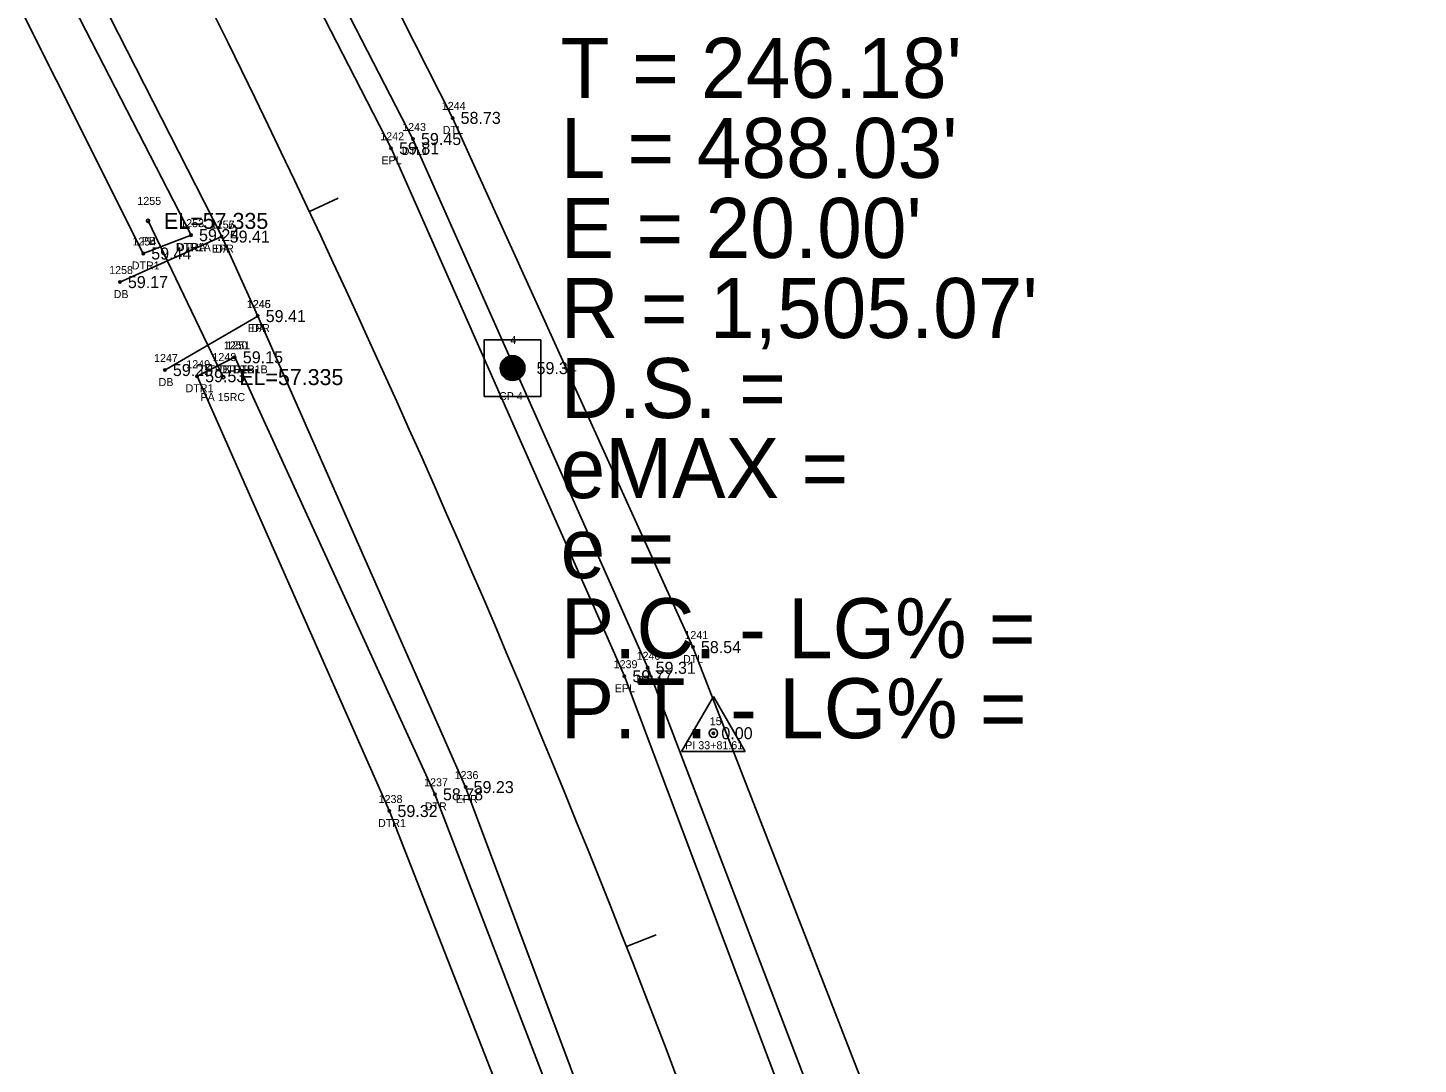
# Model space of a CAD drawing. Extents: x 2396531 to 2397633, y 770203 to 772837.
# Drawn here: x 2397412.4 to 2397586.1, y 770458.3 to 770587.8 of the extents above; entities that cross this region are included whole.
import ezdxf

# ---------------------------------------------------------------- set-up
doc = ezdxf.new("R2010")
doc.units = 0
for name, color, linetype in [('RD_EX_DR_Pipe', 7, 'Continuous'), ('RD_EX_DR_Pipe_txCode', 7, 'Continuous'), ('RD_EX_Driveway', 7, 'Continuous'), ('RD_EX_Driveway_txCode', 7, 'Continuous'), ('RD_EX_H2O', 7, 'Continuous'), ('RD_EX_H2O_txCode', 7, 'Continuous'), ('RD_EX_Road', 7, 'Continuous'), ('RD_EX_Road_txCode', 7, 'Continuous'), ('RD_EX_TX_Driveway_ELEV', 7, 'Continuous'), ('RD_EX_TX_H2O_ELEV', 7, 'Continuous'), ('RD_EX_TX_Road_ELEV', 7, 'Continuous'), ('RD_HC_Cl', 7, 'Continuous'), ('RD_HC_Data', 7, 'Continuous'), ('RD_HC_Data_Tic', 7, 'Continuous'), ('RD_HC_Survey', 7, 'Continuous'), ('RD_HC_Survey_ELEV', 7, 'Continuous'), ('RD_HC_Survey_txCode', 7, 'Continuous'), ('RD_HC_txCode', 7, 'Continuous'), ('RD_SMD_Locator', 7, 'Continuous'), ('RD_TX_Pipe_ElevEX', 7, 'Continuous')]:
    doc.layers.add(name, color=color, linetype=linetype)

msp = doc.modelspace()

# ---------------------------------------------------------------- linework, layer by layer
at = {"layer": 'RD_EX_DR_Pipe'}
msp.add_line((2397436.85, 770544.12), (2397427.46, 770563.63), dxfattribs=at)
at = {"layer": 'RD_EX_Driveway'}
for p, q in [((2397436.66, 770561.67), (2397423.94, 770555.99)), ((2397441.16, 770551.74), (2397429.56, 770545))]:
    msp.add_line(p, q, dxfattribs=at)
at = {"layer": 'RD_EX_H2O'}
for points in [[(2397586.15, 770211.51), (2397567.31, 770287.61), (2397548.79, 770357.79), (2397525.19, 770434.22), (2397495.53, 770510.39), (2397465.51, 770576.5), (2397430.55, 770645.5), (2397380.29, 770734.7), (2397327.01, 770824.44), (2397291.42, 770882.36)], [(2397579.43, 770209.93), (2397561.1, 770285.3), (2397543.19, 770356.19), (2397518.98, 770431.67), (2397489.88, 770507.8), (2397460.56, 770573.86), (2397425.02, 770642.83), (2397373.6, 770730.3), (2397319.08, 770819.92), (2397284.14, 770878.8)], [(2397432.83, 770561.85), (2397399.16, 770627.27), (2397350.75, 770711.42), (2397293.36, 770805.09), (2397257.48, 770863.23)], [(2397432.83, 770561.85), (2397426.86, 770559.56), (2397394.23, 770624.59), (2397345.55, 770708.21), (2397287.31, 770801.51), (2397251.15, 770859.33)], [(2397544.21, 770204.98), (2397524.44, 770279.37), (2397505.98, 770346.02), (2397484.83, 770420.44), (2397457.62, 770489.91), (2397433.59, 770544.23), (2397438.3, 770546.59)], [(2397549.62, 770204.86), (2397531.98, 770280.53), (2397513.08, 770348.26), (2397490.2, 770421.93), (2397463.3, 770492), (2397438.3, 770546.59)]]:
    msp.add_lwpolyline(points, dxfattribs=at)
at = {"layer": 'RD_EX_Road'}
for points in [[(2397576.88, 770209.21), (2397558.85, 770284.47), (2397539.93, 770354.87), (2397515.81, 770430.13), (2397486.97, 770506.75), (2397457.82, 770572.7), (2397422.37, 770641.75), (2397371.16, 770729.12), (2397316.57, 770818.52), (2397280.76, 770876.73)], [(2397553.19, 770205.48), (2397535.12, 770280.96), (2397517, 770349.24), (2397493.4, 770422.78), (2397467.13, 770492.9), (2397441.16, 770551.74), (2397436.66, 770561.67), (2397402.21, 770629.28), (2397353, 770712.83), (2397296, 770806.32), (2397260.16, 770864.73)]]:
    msp.add_lwpolyline(points, dxfattribs=at)
at = {"layer": 'RD_HC_Cl'}
msp.add_arc((2396086.26, 769922.93), 1505.07, 12.92958, 31.50817, dxfattribs=at)
at = {"layer": 'RD_HC_Data'}
for p, q in [((2397494.12, 770497.33), (2397498.09, 770504.21)), ((2397498.09, 770504.21), (2397502.06, 770497.33)), ((2397494.12, 770497.33), (2397502.06, 770497.33))]:
    msp.add_line(p, q, dxfattribs=at)
msp.add_circle((2397498.09, 770499.63), 0.529, dxfattribs=at)
at = {"layer": 'RD_HC_Data_Tic'}
for p, q in [((2397447.61, 770564.79), (2397451.23, 770566.49)), ((2397487.22, 770472.99), (2397490.94, 770474.45))]:
    msp.add_line(p, q, dxfattribs=at)
at = {"layer": 'RD_HC_Survey'}
for p, q in [((2397472.09, 770543.98), (2397472.09, 770546.5)), ((2397472.14, 770543.95), (2397472.14, 770546.54)), ((2397472.19, 770543.92), (2397472.19, 770546.57)), ((2397472.24, 770543.89), (2397472.24, 770546.6)), ((2397472.29, 770543.86), (2397472.29, 770546.62)), ((2397472.34, 770543.84), (2397472.34, 770546.65)), ((2397472.39, 770543.81), (2397472.39, 770546.67)), ((2397472.44, 770543.79), (2397472.44, 770546.69)), ((2397472.49, 770543.77), (2397472.49, 770546.71)), ((2397472.54, 770543.76), (2397472.54, 770546.73)), ((2397472.59, 770543.74), (2397472.59, 770546.74)), ((2397472.64, 770543.73), (2397472.64, 770546.75)), ((2397472.69, 770543.72), (2397472.69, 770546.77)), ((2397472.74, 770543.71), (2397472.74, 770546.77)), ((2397472.79, 770543.7), (2397472.79, 770546.78)), ((2397472.84, 770543.7), (2397472.84, 770546.79)), ((2397472.89, 770543.69), (2397472.89, 770546.79)), ((2397472.94, 770543.69), (2397472.94, 770546.8)), ((2397472.99, 770543.69), (2397472.99, 770546.8)), ((2397473.04, 770543.69), (2397473.04, 770546.8)), ((2397473.09, 770543.69), (2397473.09, 770546.79)), ((2397473.14, 770543.69), (2397473.14, 770546.79)), ((2397473.19, 770543.7), (2397473.19, 770546.79)), ((2397473.24, 770543.71), (2397473.24, 770546.78)), ((2397473.29, 770543.71), (2397473.29, 770546.77)), ((2397473.34, 770543.73), (2397473.34, 770546.76)), ((2397473.39, 770543.74), (2397473.39, 770546.75)), ((2397473.44, 770543.75), (2397473.44, 770546.73)), ((2397473.49, 770543.77), (2397473.49, 770546.72)), ((2397473.54, 770543.78), (2397473.54, 770546.7)), ((2397473.59, 770543.8), (2397473.59, 770546.68)), ((2397473.64, 770543.82), (2397473.64, 770546.66)), ((2397473.69, 770543.85), (2397473.69, 770546.64)), ((2397473.74, 770543.87), (2397473.74, 770546.61)), ((2397473.79, 770543.9), (2397473.79, 770546.58)), ((2397473.84, 770543.93), (2397473.84, 770546.55)), ((2397473.89, 770543.97), (2397473.89, 770546.52)), ((2397473.94, 770544), (2397473.94, 770546.48)), ((2397471.49, 770544.88), (2397471.49, 770545.6)), ((2397471.54, 770544.71), (2397471.54, 770545.77)), ((2397471.59, 770544.59), (2397471.59, 770545.89)), ((2397471.64, 770544.49), (2397471.64, 770545.99)), ((2397471.69, 770544.41), (2397471.69, 770546.08)), ((2397471.74, 770544.33), (2397471.74, 770546.15)), ((2397471.79, 770544.27), (2397471.79, 770546.22)), ((2397471.84, 770544.21), (2397471.84, 770546.28)), ((2397471.89, 770544.16), (2397471.89, 770546.33)), ((2397471.94, 770544.11), (2397471.94, 770546.38)), ((2397471.99, 770544.06), (2397471.99, 770546.42)), ((2397472.04, 770544.02), (2397472.04, 770546.46)), ((2397473.99, 770544.04), (2397473.99, 770546.44)), ((2397474.04, 770544.09), (2397474.04, 770546.4)), ((2397474.09, 770544.13), (2397474.09, 770546.35)), ((2397474.14, 770544.18), (2397474.14, 770546.3)), ((2397474.19, 770544.24), (2397474.19, 770546.24)), ((2397474.24, 770544.3), (2397474.24, 770546.18)), ((2397474.29, 770544.37), (2397474.29, 770546.11)), ((2397474.34, 770544.45), (2397474.34, 770546.03)), ((2397474.39, 770544.54), (2397474.39, 770545.94)), ((2397474.44, 770544.65), (2397474.44, 770545.83)), ((2397474.49, 770544.79), (2397474.49, 770545.69)), ((2397474.54, 770545.02), (2397474.54, 770545.47))]:
    msp.add_line(p, q, dxfattribs=at)
msp.add_lwpolyline([(2397476.54, 770548.78), (2397469.47, 770548.78), (2397469.47, 770541.71), (2397476.54, 770541.71)], close=True, dxfattribs=at)
msp.add_circle((2397473, 770545.24), 1.55, dxfattribs=at)
at = {"layer": 'RD_SMD_Locator'}
for centre, radius in [((2397465.51, 770576.5), 0.15), ((2397457.82, 770572.7), 0.15), ((2397460.56, 770573.86), 0.15), ((2397427.46, 770563.63), 0.2), ((2397432.83, 770561.85), 0.15), ((2397432.83, 770561.85), 0.15), ((2397436.66, 770561.67), 0.15), ((2397436.66, 770561.67), 0.15), ((2397426.86, 770559.56), 0.15), ((2397423.94, 770555.99), 0.15), ((2397441.16, 770551.74), 0.15), ((2397441.16, 770551.74), 0.15), ((2397438.3, 770546.59), 0.15), ((2397438.3, 770546.59), 0.15), ((2397429.56, 770545), 0.15), ((2397473, 770545.24), 0.15), ((2397433.59, 770544.23), 0.15), ((2397436.85, 770544.12), 0.2), ((2397495.53, 770510.39), 0.15), ((2397486.97, 770506.75), 0.15), ((2397489.88, 770507.8), 0.15), ((2397498.09, 770499.63), 0.15), ((2397467.13, 770492.9), 0.15), ((2397463.3, 770492), 0.15), ((2397457.62, 770489.91), 0.15)]:
    msp.add_circle(centre, radius, dxfattribs=at)

# ---------------------------------------------------------------- texts
at = {"layer": 'RD_EX_DR_Pipe_txCode'}
for s, p in [('1255', (2397426.12, 770565.63)), ('PB', (2397426.68, 770560.63)), ('1248', (2397435.5, 770546.12)), ('PA 15RC', (2397434.01, 770541.12))]:
    msp.add_text(s, height=1, dxfattribs=at).set_placement(p)
at = {"layer": 'RD_EX_Driveway_txCode'}
for s, p in [('1257', (2397435.31, 770562.67)), ('DA', (2397435.86, 770559.67)), ('1258', (2397422.6, 770556.99)), ('DB', (2397423.16, 770553.99)), ('1246', (2397439.79, 770552.74)), ('DA', (2397440.37, 770549.74)), ('1247', (2397428.21, 770546)), ('DB', (2397428.78, 770543))]:
    msp.add_text(s, height=1, dxfattribs=at).set_placement(p)
at = {"layer": 'RD_EX_H2O_txCode'}
for s, p in [('1244', (2397464.16, 770577.5)), ('1243', (2397459.21, 770574.86)), ('DTL', (2397464.27, 770574.5)), ('DTL1', (2397459.15, 770571.86)), ('1252', (2397431.48, 770562.85)), ('1253', (2397431.48, 770562.85)), ('1254', (2397425.51, 770560.56)), ('DTR1A', (2397430.91, 770559.85)), ('DTRA', (2397431.07, 770559.85)), ('DTR1', (2397425.42, 770557.56)), ('1250', (2397436.92, 770547.59)), ('1251', (2397437.24, 770547.59)), ('1249', (2397432.24, 770545.23)), ('DTRB DTR1B', (2397434.02, 770544.59)), ('DTR1B', (2397436.4, 770544.59)), ('DTR1', (2397432.15, 770542.23)), ('1241', (2397494.47, 770511.39)), ('1240', (2397488.5, 770508.8)), ('DTL', (2397494.29, 770508.39)), ('DTL1', (2397488.48, 770505.8)), ('1237', (2397461.95, 770493)), ('1238', (2397456.27, 770490.91)), ('DTR', (2397462.03, 770490)), ('DTR1', (2397456.19, 770487.91))]:
    msp.add_text(s, height=1, dxfattribs=at).set_placement(p)
at = {"layer": 'RD_EX_Road_txCode'}
for s, p in [('1242', (2397456.47, 770573.7)), ('EPL', (2397456.61, 770570.7)), ('1256', (2397435.29, 770562.67)), ('EPR', (2397435.43, 770559.67)), ('1245', (2397439.82, 770552.74)), ('EPR', (2397439.93, 770549.74)), ('1239', (2397485.63, 770507.75)), ('EPL', (2397485.77, 770504.75)), ('1236', (2397465.76, 770493.9)), ('EPR', (2397465.9, 770490.9))]:
    msp.add_text(s, height=1, dxfattribs=at).set_placement(p)
at = {"layer": 'RD_EX_TX_Driveway_ELEV'}
for s, p in [('59.41', (2397437.66, 770560.92)), ('59.17', (2397424.94, 770555.24)), ('59.41', (2397442.16, 770550.99)), ('59.25', (2397430.56, 770544.25))]:
    msp.add_text(s, height=1.5, dxfattribs=at).set_placement(p)
at = {"layer": 'RD_EX_TX_H2O_ELEV'}
for s, p in [('58.73', (2397466.51, 770575.75)), ('59.45', (2397461.56, 770573.11)), ('59.24', (2397433.83, 770561.1)), ('59.24', (2397433.83, 770561.1)), ('59.44', (2397427.86, 770558.81)), ('59.15', (2397439.3, 770545.84)), ('59.15', (2397439.3, 770545.84)), ('59.53', (2397434.59, 770543.48)), ('58.54', (2397496.53, 770509.64)), ('59.31', (2397490.88, 770507.05)), ('58.78', (2397464.3, 770491.25)), ('59.32', (2397458.62, 770489.16))]:
    msp.add_text(s, height=1.5, dxfattribs=at).set_placement(p)
at = {"layer": 'RD_EX_TX_Road_ELEV'}
for s, p in [('59.81', (2397458.82, 770571.95)), ('59.41', (2397437.66, 770560.92)), ('59.41', (2397442.16, 770550.99)), ('59.77', (2397487.97, 770506)), ('59.23', (2397468.13, 770492.15))]:
    msp.add_text(s, height=1.5, dxfattribs=at).set_placement(p)
at = {"layer": 'RD_HC_Data'}
for s, p in [("T = 246.18'", (2397479, 770579)), ("L = 488.03'", (2397479, 770569)), ("E = 20.00'", (2397479, 770559)), ("R = 1,505.07'", (2397479, 770549)), ('D.S. = ', (2397479, 770539)), ('eMAX = ', (2397479, 770529)), ('e = ', (2397479, 770519)), ('P.C. - LG% = ', (2397479, 770509)), ('P.T. - LG% = ', (2397479, 770499))]:
    msp.add_text(s, height=7.5, dxfattribs=at).set_placement(p)
at = {"layer": 'RD_HC_Survey_ELEV'}
for s, p in [('59.34', (2397476, 770544.49)), ('0.00', (2397499.09, 770498.88))]:
    msp.add_text(s, height=1.5, dxfattribs=at).set_placement(p)
at = {"layer": 'RD_HC_Survey_txCode'}
for s, p in [('4', (2397472.72, 770548.24)), ('CP 4', (2397471.3, 770541.24))]:
    msp.add_text(s, height=1, dxfattribs=at).set_placement(p)
at = {"layer": 'RD_HC_txCode'}
for s, p in [('15', (2397497.64, 770500.63)), ('PI 33+81.61', (2397494.57, 770497.63))]:
    msp.add_text(s, height=1, dxfattribs=at).set_placement(p)
at = {"layer": 'RD_TX_Pipe_ElevEX'}
for p in [(2397429.46, 770562.63), (2397438.85, 770543.12)]:
    msp.add_text('EL=57.335', height=2, dxfattribs=at).set_placement(p)

doc.saveas('drawing.dxf')
